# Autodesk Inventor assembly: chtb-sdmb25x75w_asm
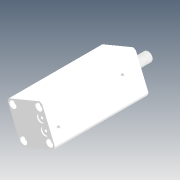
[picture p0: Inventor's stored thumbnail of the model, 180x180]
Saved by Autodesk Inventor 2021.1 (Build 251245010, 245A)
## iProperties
Company: Microsoft
Created: 2018-05
Part Number: chtb-sdmb25x75w_asm
Description: STEP AP214
Document SubType Name: Assembly
Designer: user
Title: chtb-sdmb25x75w_asm.STEP
Author: Windows
Revision Number: ÈÎºÎ
Sending System: SolidWorks 2015
Preprocessor: SwSTEP 2.0
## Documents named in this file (4)
- D:\Vault_2016\Projekty\Clamptek\Hydraulic\CHTB\CHTB-25\Inventor\chtb-sdmb25x75w\chtb-sdmb25x75w_asm.iam
- D:\Vault_2016\Projekty\Clamptek\Hydraulic\CHTB\CHTB-25\Inventor\chtb-sdmb25x75w\CHTB-25QG.ipt
- D:\Vault_2016\Projekty\Clamptek\Hydraulic\CHTB\CHTB-25\Inventor\chtb-sdmb25x75w\CHTB-SDMB25X75NBT.ipt
- D:\Vault_2016\Projekty\Clamptek\Hydraulic\CHTB\CHTB-25\Inventor\chtb-sdmb25x75w\CHTB-SDMB25X75WHSG.ipt
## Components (3 placed, 3 different names)
1. CHTB-25QG_1
2. CHTB-SDMB25X75NBT_2
3. CHTB-SDMB25X75WHSG_3
